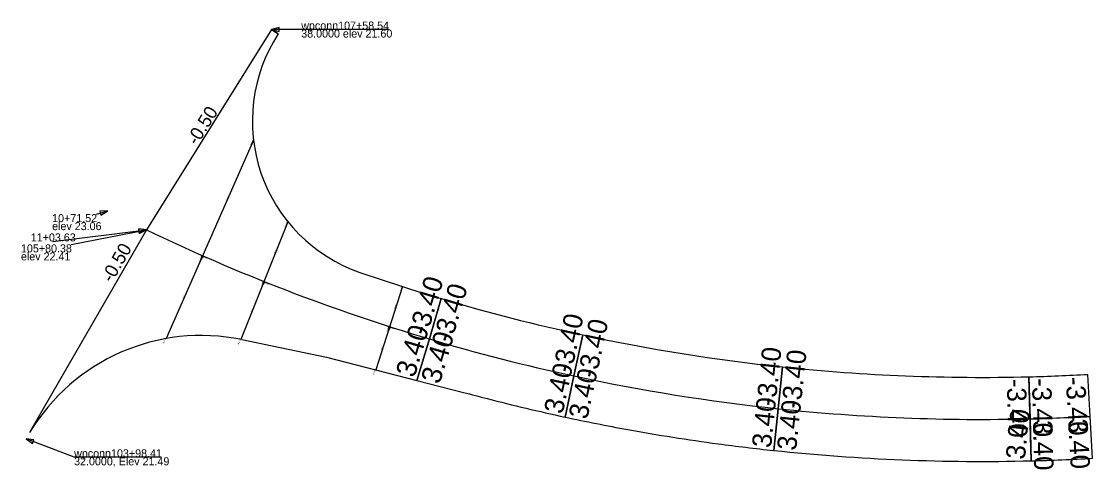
# Model space of a CAD drawing. Extents: x -26 to 2346399, y -10 to 367426.
# Drawn here: x 2345597 to 2346399, y 367090 to 367426 of the extents above; entities that cross this region are included whole.
import ezdxf

# ---------------------------------------------------------------- set-up
doc = ezdxf.new("R2010")
doc.units = 0
for name, color, linetype in [('Default', 7, 'Continuous'), ('RD_PD_RW_TX', 7, 'Continuous'), ('RD_PD_SuperShp_WB_526', 7, 'Continuous'), ('RD_Sketch4', 7, 'Continuous')]:
    doc.layers.add(name, color=color, linetype=linetype)

msp = doc.modelspace()

# ---------------------------------------------------------------- linework, layer by layer
at = {"layer": 'Default'}
for p, q in [((2345784.16, 367419.48), (2345789.19, 367416.21)), ((2346353.39, 367096.28), (2346351.82, 367159.26))]:
    msp.add_line(p, q, dxfattribs=at)
at = {"layer": 'RD_PD_RW_TX'}
for p, q in [((2345872.04, 367419.48), (2345806.47, 367419.48)), ((2345701.23, 367098.91), (2345636.27, 367098.91))]:
    msp.add_line(p, q, dxfattribs=at)
for points in [[(2345789.95, 367421.03), (2345784.16, 367419.48), (2345789.95, 367417.93)], [(2345656.41, 367280.48), (2345661.59, 367283.52), (2345655.59, 367283.48)], [(2345685, 367266.72), (2345690.4, 367269.34), (2345684.41, 367269.77)], [(2345684.83, 367267.09), (2345690.4, 367269.34), (2345684.45, 367270.17)], [(2345606.19, 367112.06), (2345600.22, 367112.64), (2345605.1, 367109.15)]]:
    msp.add_lwpolyline(points, close=True, dxfattribs=at)
for points in [[(2345872.04, 367419.48), (2345784.16, 367419.48)], [(2345653.05, 367281.17), (2345661.59, 367283.52)], [(2345620.25, 367260.7), (2345690.4, 367269.34)], [(2345633.99, 367258.48), (2345690.4, 367269.34)], [(2345636.27, 367099.1), (2345600.22, 367112.64)]]:
    msp.add_lwpolyline(points, dxfattribs=at)
at = {"layer": 'RD_PD_SuperShp_WB_526'}
for p, q in [((2345770.66, 367336.69), (2345705.22, 367187.87)), ((2345796.5, 367275.4), (2345761.31, 367187.23)), ((2345882.36, 367226.82), (2345862.32, 367164.45))]:
    msp.add_line(p, q, dxfattribs=at)
for points in [[(2345732.54, 367250), (2345731.46, 367249.47), (2345731.87, 367249.29), (2345731.27, 367247.92), (2345731.86, 367247.66), (2345732.46, 367249.03), (2345732.88, 367248.85)], [(2345778.65, 367230.67), (2345777.59, 367230.1), (2345778.01, 367229.93), (2345777.45, 367228.54), (2345778.05, 367228.3), (2345778.61, 367229.7), (2345779.02, 367229.53)], [(2345872.73, 367196.83), (2345871.71, 367196.19), (2345872.14, 367196.05), (2345871.68, 367194.62), (2345872.29, 367194.42), (2345872.75, 367195.85), (2345873.18, 367195.71)]]:
    msp.add_lwpolyline(points, close=True, dxfattribs=at)
at = {"layer": 'RD_Sketch4'}
for p, q in [((2345784.16, 367419.48), (2345690.4, 367269.34)), ((2345789.19, 367416.21), (2345784.16, 367419.48)), ((2345690.4, 367269.34), (2345602.95, 367117.38)), ((2345902.46, 367187.62), (2345911.45, 367217.81)), ((2345911.45, 367217.81), (2345902.46, 367187.62)), ((2345761.93, 367187.1), (2345825.39, 367173.98)), ((2345893.19, 367156.48), (2345902.46, 367187.62)), ((2345902.46, 367187.62), (2345893.19, 367156.48)), ((2346010.81, 367159.86), (2346017.45, 367190.66)), ((2346017.45, 367190.66), (2346010.81, 367159.86)), ((2345825.39, 367173.98), (2345893.19, 367156.48)), ((2346163.88, 367135.35), (2346167.19, 367166.68)), ((2346167.19, 367166.68), (2346163.88, 367135.35)), ((2346397.7, 367129.6), (2346395.93, 367161.05)), ((2345893.19, 367156.48), (2345928.05, 367147.59)), ((2346004.18, 367129.07), (2346010.81, 367159.86)), ((2346010.81, 367159.86), (2346004.18, 367129.07)), ((2346352.61, 367127.77), (2346351.82, 367159.26)), ((2346351.82, 367159.26), (2346352.61, 367127.77)), ((2346160.57, 367104.03), (2346163.88, 367135.35)), ((2346163.88, 367135.35), (2346160.57, 367104.03)), ((2346399.46, 367098.15), (2346397.7, 367129.6)), ((2346353.39, 367096.28), (2346352.61, 367127.77)), ((2346352.61, 367127.77), (2346353.39, 367096.28))]:
    msp.add_line(p, q, dxfattribs=at)
for centre, radius, start, end in [((2345889.82, 367350.84), 120, 146.99408, 250.82997), ((2346316.34, 368577.71), 1450.39, 244.43276, 253.41985), ((2346316.34, 368577.71), 1450.39, 244.43276, 253.41985), ((2346316.34, 368577.71), 1418.89, 250.82997, 253.41985), ((2346316.34, 368577.71), 1418.89, 253.41985, 257.83946), ((2345731.57, 367040.21), 150, 78.32216, 149.03728), ((2346316.34, 368577.71), 1450.39, 253.41985, 257.83946), ((2346316.34, 368577.71), 1450.39, 253.41985, 257.83946), ((2346316.34, 368577.71), 1418.89, 257.83946, 263.96608), ((2346316.34, 368577.71), 1418.89, 263.96608, 271.43275), ((2346316.34, 368577.71), 1418.89, 271.43275, 273.21556), ((2346316.34, 368577.71), 1450.39, 257.83946, 263.96608), ((2346316.34, 368577.71), 1450.39, 257.83946, 263.96608), ((2346316.34, 368577.71), 1481.89, 254.80964, 255.52131), ((2346316.34, 368577.71), 1481.89, 255.52131, 257.83946), ((2346316.34, 368577.71), 1481.89, 257.83946, 259.69182), ((2346316.34, 368577.71), 1450.39, 263.96608, 271.43275), ((2346316.34, 368577.71), 1450.39, 263.96608, 271.43275), ((2346316.34, 368577.71), 1450.39, 271.43275, 273.21556), ((2346316.34, 368577.71), 1450.39, 271.43275, 273.21556), ((2346316.34, 368577.71), 1481.89, 259.69182, 262.34048), ((2346316.34, 368577.71), 1481.89, 262.34048, 263.96608), ((2346316.34, 368577.71), 1481.89, 263.96608, 271.43275), ((2346316.34, 368577.71), 1481.89, 271.43275, 273.21556)]:
    msp.add_arc(centre, radius, start, end, dxfattribs=at)

# ---------------------------------------------------------------- texts
at = {"layer": 'Default'}
msp.add_text('105+80.38', height=0.00975, rotation=90, dxfattribs=at).set_placement((2345661.72, 367259.63))
msp.add_text('-.004', height=0.00975, dxfattribs=at).set_placement((2345654.55, 367222.66))
at = {"layer": 'RD_PD_RW_TX'}
for s, p in [('wpconn107+58.54', (2345806.47, 367419.48)), ('38.0000 elev 21.60', (2345806.47, 367413.48)), ('10+71.52', (2345619.79, 367275.16)), ('elev 23.06', (2345619.79, 367269.16)), ('11+03.63', (2345603.81, 367260.7)), ('105+80.38', (2345596.45, 367252.48)), ('elev 22.41', (2345596.45, 367246.48)), ('wpconn103+98.41', (2345636.27, 367098.91)), ('32.0000, Elev 21.49', (2345636.27, 367092.91))]:
    msp.add_text(s, height=6, dxfattribs=at).set_placement(p)
at = {"layer": 'RD_PD_SuperShp_WB_526'}
for s, rotation, p in [('20.502', 246.26455, (2345769.74, 367337.1)), ('-0.97', 246.26455, (2345751.31, 367295.18)), ('19.691', 248.23973, (2345795.57, 367275.77)), ('21.421', 246.26455, (2345731.62, 367250.4)), ('21.421', 336.26455, (2345732.14, 367249.09)), ('-1.64', 248.23973, (2345787.22, 367254.85)), ('20.482', 248.23973, (2345777.72, 367231.04)), ('20.482', 338.23973, (2345778.28, 367229.74)), ('18.600', 252.1901, (2345881.41, 367227.12)), ('0.37', 246.26455, (2345718.5, 367220.55)), ('1.21', 248.23973, (2345769.51, 367210.46)), ('-2.98', 252.1901, (2345877.07, 367213.61)), ('19.540', 252.1901, (2345871.77, 367197.13)), ('19.540', 342.1901, (2345872.42, 367195.87)), ('21.675', 246.26455, (2345704.31, 367188.28)), ('21.048', 248.23973, (2345760.38, 367187.6)), ('2.88', 252.1901, (2345866.98, 367182.21)), ('20.519', 252.1901, (2345861.37, 367164.75))]:
    msp.add_text(s, height=1, rotation=rotation, dxfattribs=at).set_placement(p)
at = {"layer": 'RD_Sketch4'}
for s, height, rotation, p in [('-0.50', 10, 58.01568, (2345728.37, 367332.02)), ('-0.50', 10, 60.08072, (2345664.68, 367229.16)), ('-3.40', 14.49, 73.41985, (2345900.71, 367189.46)), ('-3.40', 14.49, 73.41985, (2345918.82, 367184.07)), ('-3.40', 14.49, 77.83946, (2346008.92, 367161.56)), ('-3.40', 14.49, 77.83946, (2346027.4, 367157.58)), ('3.40', 14.949, 73.41985, (2345891.29, 367158.03)), ('3.40', 14.949, 73.41985, (2345910.17, 367153.18)), ('-3.40', 14.49, 83.96608, (2346161.82, 367136.84)), ('-3.40', 14.49, 83.96608, (2346180.62, 367134.85)), ('3.40', 14.49, 77.83946, (2346002.29, 367130.77)), ('3.40', 14.49, 77.83946, (2346020.77, 367126.79)), ('-3.40', 14.49, 271.43275, (2346335.16, 367157.59)), ('-3.40', 14.49, 271.43275, (2346354.05, 367158.06)), ('-3.40', 14.49, 273.21556, (2346379.33, 367158.86)), ('3.40', 14.49, 83.96608, (2346158.51, 367105.51)), ('3.40', 14.49, 83.96608, (2346177.3, 367103.53)), ('3.40', 14.49, 83.96608, (2346348.68, 367096.82)), ('3.40', 14.49, 271.43275, (2346354.84, 367126.57)), ('3.40', 14.49, 273.21556, (2346381.1, 367127.41))]:
    msp.add_text(s, height=height, rotation=rotation, dxfattribs=at).set_placement(p)

doc.saveas('drawing.dxf')
